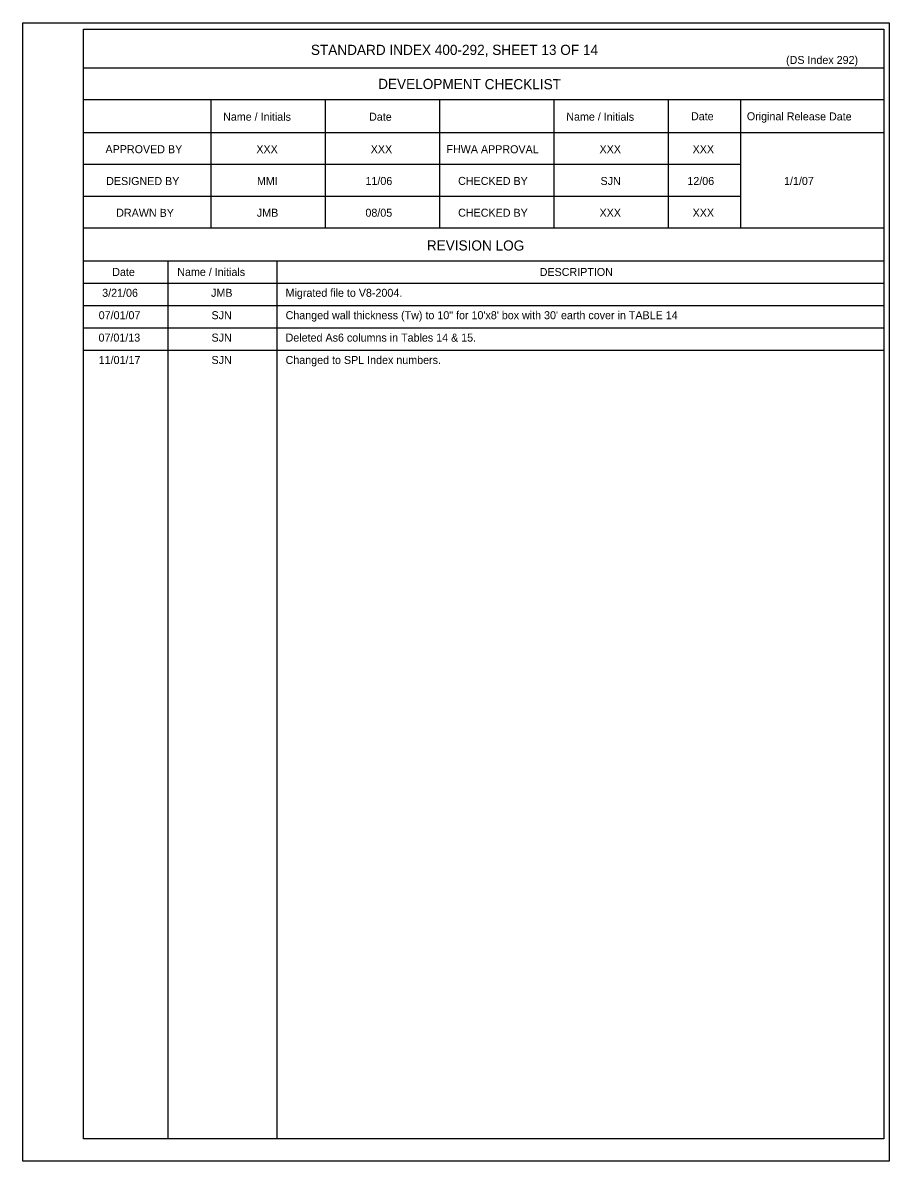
# Model space of a CAD drawing. Extents: x 10351.18 to 10353.4, y 76371.55 to 76372.62.
# Drawn here: x 10352.716 to 10353.397, y 76371.667 to 76372.563 of the extents above; entities that cross this region are included whole.
import ezdxf

# ---------------------------------------------------------------- set-up
doc = ezdxf.new("R2010")
doc.units = 0
doc.layers.add('AdhocPoint_dp', color=7, linetype='Continuous')
doc.layers.add('Border', color=7, linetype='Continuous')

msp = doc.modelspace()

# ---------------------------------------------------------------- linework, layer by layer
at = {"layer": 'Border'}
for p, q in [((10353.39322, 76372.52706), (10352.76364, 76372.52706)), ((10353.39322, 76372.50206), (10352.76364, 76372.50206)), ((10352.86364, 76372.50206), (10352.86364, 76372.40119)), ((10352.95364, 76372.50206), (10352.95364, 76372.40119)), ((10353.04364, 76372.50206), (10353.04364, 76372.40119)), ((10353.13363, 76372.50206), (10353.13363, 76372.40119)), ((10353.22363, 76372.50206), (10353.22363, 76372.40119)), ((10353.28035, 76372.50206), (10353.28035, 76372.40119)), ((10353.39322, 76372.47619), (10352.76364, 76372.47619)), ((10353.28035, 76372.45119), (10352.76364, 76372.45119)), ((10353.28035, 76372.42619), (10352.76364, 76372.42619)), ((10353.39322, 76372.40119), (10352.76364, 76372.40119)), ((10353.39322, 76372.37532), (10352.76364, 76372.37532)), ((10352.8299, 76372.37532), (10352.8299, 76371.68449)), ((10352.91559, 76372.37532), (10352.91559, 76371.68449)), ((10353.39322, 76372.3577), (10352.76364, 76372.3577)), ((10353.39322, 76372.34008), (10352.76364, 76372.34008)), ((10353.39322, 76372.32247), (10352.76364, 76372.32247)), ((10353.39322, 76372.30485), (10352.76364, 76372.30485)), ((10352.71581, 76371.66695), (10352.71581, 76371.66695))]:
    msp.add_line(p, q, dxfattribs=at)
for points in [[(10352.71581, 76372.56278), (10353.39748, 76372.56278), (10353.39748, 76371.66695), (10352.71581, 76371.66695)], [(10352.76364, 76372.5577), (10353.39322, 76372.5577), (10353.39322, 76371.68449), (10352.76364, 76371.68449)]]:
    msp.add_lwpolyline(points, close=True, dxfattribs=at)

# ---------------------------------------------------------------- texts
at = {"layer": 'AdhocPoint_dp'}
for s, height, p in [('STANDARD INDEX 400-292, SHEET 13 OF 14', 0.008, (10352.94247, 76372.53745)), ('(DS Index 292)', 0.0063, (10353.31632, 76372.53037)), ('XXX', 0.0063, (10352.89957, 76372.46015)), ('XXX', 0.0063, (10352.98957, 76372.46015)), ('XXX', 0.0063, (10353.16957, 76372.46015)), ('XXX', 0.0063, (10353.2428, 76372.46015)), ('MMI', 0.0063, (10352.90007, 76372.43515)), ('11/06', 0.0063, (10352.98543, 76372.43515)), ('SJN', 0.0063, (10353.17034, 76372.43515)), ('12/06', 0.0063, (10353.23866, 76372.43515)), ('1/1/07', 0.0063, (10353.31473, 76372.43515)), ('JMB', 0.0063, (10352.89998, 76372.41015)), ('08/05', 0.0063, (10352.98539, 76372.41015)), ('XXX', 0.0063, (10353.16957, 76372.41015)), ('XXX', 0.0063, (10353.2428, 76372.41015)), ('DESCRIPTION', 0.0063, (10353.1225, 76372.36354)), ('3/21/06', 0.0063, (10352.7783, 76372.34714)), ('JMB', 0.0063, (10352.86394, 76372.34714)), ('Migrated file to V8-2004.', 0.0063, (10352.92258, 76372.34714)), ('07/01/07', 0.0063, (10352.77555, 76372.32952)), ('SJN', 0.0063, (10352.8643, 76372.32952)), ('Changed wall thickness (Tw) to 10" for 10\'x8\' box with 30\' earth cover in TABLE 14', 0.0063, (10352.92258, 76372.32952)), ('07/01/13', 0.0063, (10352.7754, 76372.3119)), ('SJN', 0.0063, (10352.8643, 76372.3119)), ('Deleted As6 columns in Tables 14 & 15.', 0.0063, (10352.92258, 76372.3119)), ('11/01/17', 0.0063, (10352.77555, 76372.29429)), ('SJN', 0.0063, (10352.8643, 76372.29429)), ('Changed to SPL Index numbers.', 0.0063, (10352.92258, 76372.29429))]:
    msp.add_text(s, height=height, dxfattribs=at).set_placement(p)
for s, height, p in [('DEVELOPMENT CHECKLIST', 0.008, (10352.99538, 76372.51071)), ('Name / Initials', 0.0063, (10352.87341, 76372.48578)), ('Date', 0.0063, (10352.98824, 76372.48573)), ('Name / Initials', 0.0063, (10353.1434, 76372.48578)), ('Date', 0.0063, (10353.24152, 76372.48609)), ('Original Release Date', 0.0063, (10353.28547, 76372.48608)), ('APPROVED BY', 0.0063, (10352.78088, 76372.46021)), ('FHWA APPROVAL', 0.0063, (10353.04911, 76372.46021)), ('DESIGNED BY', 0.0063, (10352.78141, 76372.43515)), ('CHECKED BY', 0.0063, (10353.05832, 76372.43521)), ('DRAWN BY', 0.0063, (10352.78931, 76372.41015)), ('CHECKED BY', 0.0063, (10353.05832, 76372.41021)), ('REVISION LOG', 0.008, (10353.03367, 76372.38365)), ('Date', 0.0063, (10352.78621, 76372.36356)), ('Name / Initials', 0.0063, (10352.83735, 76372.36361))]:
    msp.add_text(s, height=height, rotation=359.87563, dxfattribs=at).set_placement(p)

doc.saveas('drawing.dxf')
